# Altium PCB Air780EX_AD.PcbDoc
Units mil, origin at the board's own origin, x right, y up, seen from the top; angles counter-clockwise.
Board outline 6000 x 4000 mil, 4 copper layers (Top, Mid-Layer 1, Mid-Layer 2, Bottom), stack 35.4 mil thick; 1 components, 0 nets, 54 pads, 0 vias.
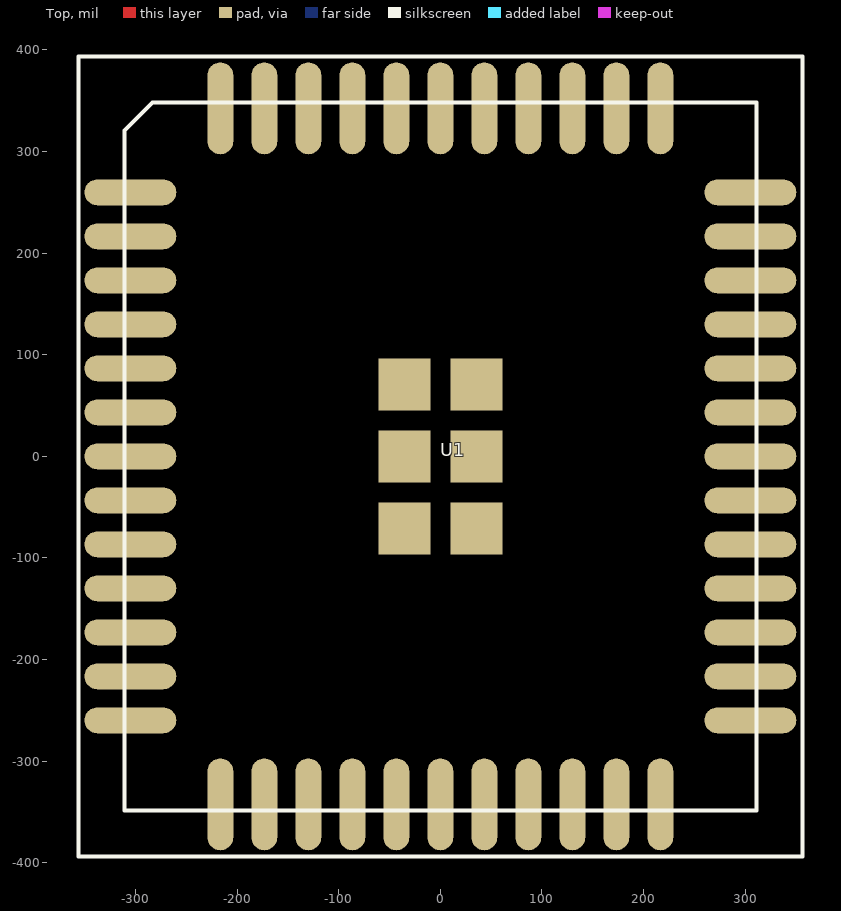
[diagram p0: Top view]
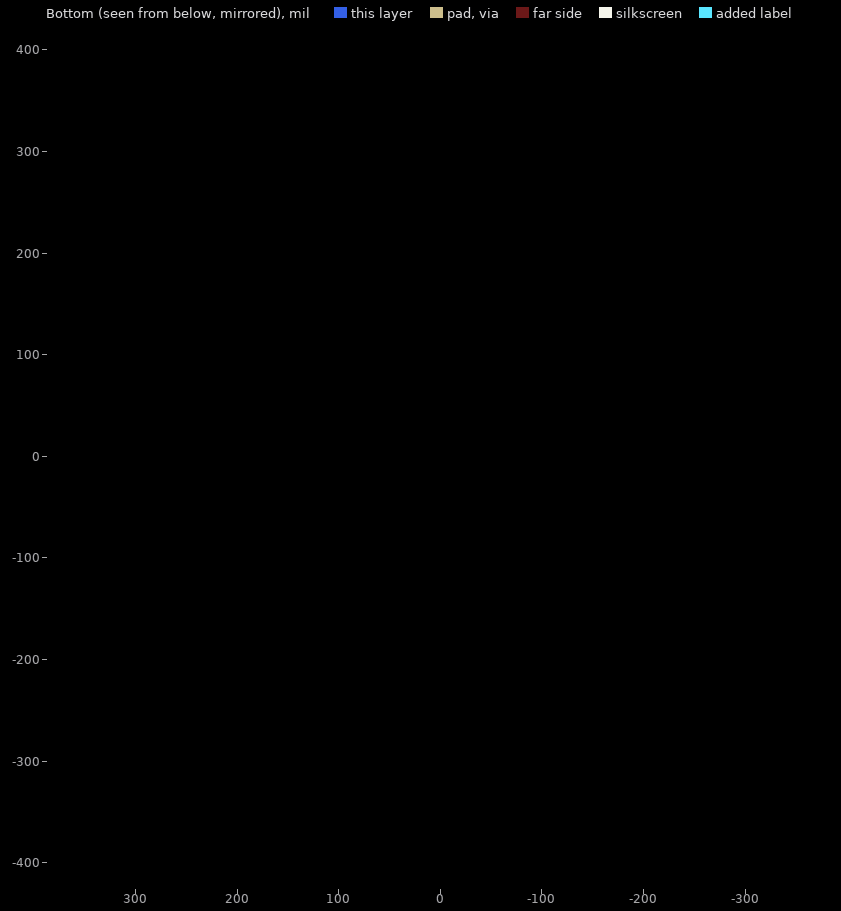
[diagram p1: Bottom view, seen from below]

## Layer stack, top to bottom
Top: signal copper 1.35
Dielectric: dielectric 10, FR-4, Dk 4.3
Mid-Layer 1: signal copper 1.35
Dielectric: dielectric 10, FR-4, Dk 4.3
Mid-Layer 2: signal copper 1.35
Dielectric: dielectric 10, FR-4, Dk 4.3
Bottom: signal copper 1.35

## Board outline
-9000,-9000 -3000,-9000 -3000,-5000 -9000,-5000

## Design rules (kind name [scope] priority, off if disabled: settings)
Clearance "'Default' PADS rule_18" [All] p1: gap=6
Clearance "'Default' PADS rule_15" [IsVia vs IsVia] p2: gap=6
ComponentClearance "'Default' PADS rule_12" [All] p1: gap=6 collisioncheckmode=3 verticalgap=10 showdistances=FALSE
FlightTimeFalling "'Default' PADS rule_10" [All] p1: maximum=10.00
FlightTimeRising "'Default' PADS rule_9" [All] p1: maximum=10.00
Length "'Default' PADS rule_5" [All] p1: maxlimit=50000 minlimit=0
MatchedLengths "'Default' PADS rule_11" [InNetClass('All Nets')] p1: tolerance=200 checknetsindiffpair=TRUE checkdiffpairvsdiffpair=TRUE checkothers=TRUE
MaxMinImpedance "'Default' PADS rule_8" [All] p1: minimum=50.00 maximum=150.0
ParallelSegment "'Default' PADS rule_7" [All] p1: limit=1000 gap=200
ParallelSegment "'Default' PADS rule_6" [All] p2: limit=1000 gap=200
PlaneClearance "'Default' PADS rule_14" [All] p1: clearance=6
PlaneConnect "Power Plane Connect Style - Via from round thru-hole global defaults" [IsVia] p1: planeconnectstyle=Relief reliefexpansion=20 reliefentries=4 reliefconductorwidth=15 reliefairgap=10
PlaneConnect "Power Plane Connect Style - Round thru-hole pad from global defaults" [IsPad And OnMultiLayer And (PadShape_MidLayer1 = 'Round') And (PadXSize_MidLayer1 = PadYSize_MidLayer1)] p2: planeconnectstyle=Relief reliefexpansion=20 reliefentries=4 reliefconductorwidth=15 reliefairgap=10
PlaneConnect "Power Plane Connect Style - Square thru-hole pad from global defaults" [IsPad And OnMultiLayer And ((PadShape_MidLayer1 = 'Rectangular') Or (PadShape_MidLayer1 = 'Octagonal') Or (PadShape_MidLayer1 = 'Rounded Rectangle')) And (PadXSize_MidLayer1 = PadYSize_MidLayer1)] p3: planeconnectstyle=Relief reliefexpansion=20 reliefentries=4 reliefconductorwidth=15 reliefairgap=10
PlaneConnect "Power Plane Connect Style - Rect thru-hole pad from global defaults" [IsPad And OnMultiLayer And ((PadShape_MidLayer1 = 'Rectangular') Or (PadShape_MidLayer1 = 'Octagonal') Or (PadShape_MidLayer1 = 'Rounded Rectangle')) And (PadXSize_MidLayer1 <> PadYSize_MidLayer1)] p4: planeconnectstyle=Relief reliefexpansion=20 reliefentries=4 reliefconductorwidth=15 reliefairgap=10
PlaneConnect "Power Plane Connect Style - Square-rect thru-hole pad from global defaults" [IsPad And OnMultiLayer And (PadShape_MidLayer1 = 'Rounded Rectangle') And (PadXSize_MidLayer1 = PadYSize_MidLayer1) And (Pad_CornerRadius_MidLayer1 = '0%')] p5: planeconnectstyle=Relief reliefexpansion=20 reliefentries=4 reliefconductorwidth=15 reliefairgap=10
PlaneConnect "Power Plane Connect Style - Oval thru-hole pad from global defaults" [IsPad And OnMultiLayer And (PadShape_MidLayer1 = 'Round') And (PadXSize_MidLayer1 <> PadYSize_MidLayer1)] p6: planeconnectstyle=Relief reliefexpansion=20 reliefentries=4 reliefconductorwidth=15 reliefairgap=10
PlaneConnect "Power Plane Connect Style - Round-oval thru-hole pad from global defaults" [IsPad And OnMultiLayer And (PadShape_MidLayer1 = 'Rounded Rectangle') And (PadXSize_MidLayer1 = PadYSize_MidLayer1) And (Pad_CornerRadius_MidLayer1 = '100%')] p7: planeconnectstyle=Relief reliefexpansion=20 reliefentries=4 reliefconductorwidth=15 reliefairgap=10
PolygonConnect "Polygon Connect Style - Bottom Round SMD from global defaults" [IsSMTPin And (PadShape_BottomLayer = 'Round') And (PadXSize_BottomLayer = PADYSize_BottomLayer) vs Layer = 'Bottom'] p1: connectstyle=Relief reliefconductorwidth=10 reliefentries=4 polygonreliefangle="45 Angle" airgapwidth=10
PolygonConnect "Polygon Connect Style - Top Round SMD from global defaults" [IsSMTPin And (PadShape_TopLayer = 'Round') And (PadXSize_TopLayer = PADYSize_TopLayer) vs Layer = 'Top'] p2: connectstyle=Relief reliefconductorwidth=10 reliefentries=4 polygonreliefangle="45 Angle" airgapwidth=10
PolygonConnect "Polygon Connect Style - Bottom Square SMD from global defaults 1" [IsSMTPin And (PadShape_BottomLayer = 'Rectangular') And (PadXSize_BottomLayer = PADYSize_BottomLayer) vs Layer = 'Bottom'] p3: connectstyle=Relief reliefconductorwidth=10 reliefentries=4 polygonreliefangle="45 Angle" airgapwidth=10
PolygonConnect "Polygon Connect Style - Bottom Square SMD from global defaults 2" [IsSMTPin And (PadShape_BottomLayer = 'Octagonal') And (PadXSize_BottomLayer = PADYSize_BottomLayer) vs Layer = 'Bottom'] p4: connectstyle=Relief reliefconductorwidth=10 reliefentries=4 polygonreliefangle="45 Angle" airgapwidth=10
PolygonConnect "Polygon Connect Style - Bottom Square SMD from global defaults 3" [IsSMTPin And (PadShape_BottomLayer = 'Rounded Rectangle') And (PadXSize_BottomLayer = PADYSize_BottomLayer) vs Layer = 'Bottom'] p5: connectstyle=Relief reliefconductorwidth=10 reliefentries=4 polygonreliefangle="45 Angle" airgapwidth=10
PolygonConnect "Polygon Connect Style - Top Square SMD from global defaults 1" [IsSMTPin And (PadShape_TopLayer = 'Rectangular') And (PadXSize_TopLayer = PADYSize_TopLayer) vs Layer = 'Top'] p6: connectstyle=Relief reliefconductorwidth=10 reliefentries=4 polygonreliefangle="45 Angle" airgapwidth=10
PolygonConnect "Polygon Connect Style - Top Square SMD from global defaults 2" [IsSMTPin And (PadShape_TopLayer = 'Octagonal') And (PadXSize_TopLayer = PADYSize_TopLayer) vs Layer = 'Top'] p7: connectstyle=Relief reliefconductorwidth=10 reliefentries=4 polygonreliefangle="45 Angle" airgapwidth=10
PolygonConnect "Polygon Connect Style - Top Square SMD from global defaults 3" [IsSMTPin And (PadShape_TopLayer = 'Rounded Rectangle') And (PadXSize_TopLayer = PADYSize_TopLayer) vs Layer = 'Top'] p8: connectstyle=Relief reliefconductorwidth=10 reliefentries=4 polygonreliefangle="45 Angle" airgapwidth=10
PolygonConnect "Polygon Connect Style - Bottom Rect SMD from global defaults 1" [IsSMTPin And (PadShape_BottomLayer = 'Rectangular') And (PadXSize_BottomLayer <> PADYSize_BottomLayer) vs Layer = 'Bottom'] p9: connectstyle=Relief reliefconductorwidth=10 reliefentries=4 polygonreliefangle="45 Angle" airgapwidth=10
PolygonConnect "Polygon Connect Style - Bottom Rect SMD from global defaults 2" [IsSMTPin And (PadShape_BottomLayer = 'Octagonal') And (PadXSize_BottomLayer <> PADYSize_BottomLayer) vs Layer = 'Bottom'] p10: connectstyle=Relief reliefconductorwidth=10 reliefentries=4 polygonreliefangle="45 Angle" airgapwidth=10
PolygonConnect "Polygon Connect Style - Bottom Rect SMD from global defaults 3" [IsSMTPin And (PadShape_BottomLayer = 'Rounded Rectangle') And (PadXSize_BottomLayer <> PADYSize_BottomLayer) vs Layer = 'Bottom'] p11: connectstyle=Relief reliefconductorwidth=10 reliefentries=4 polygonreliefangle="45 Angle" airgapwidth=10
PolygonConnect "Polygon Connect Style - Bottom Square-rect SMD pad from global defaults" [IsSMTPin And (PadShape_BottomLayer = 'Rounded Rectangle') And (PadXSize_BottomLayer = PADYSize_BottomLayer) And (Pad_CornerRadius_BottomLayer = '0%') vs Layer = 'Bottom'] p12: connectstyle=Relief reliefconductorwidth=10 reliefentries=4 polygonreliefangle="45 Angle" airgapwidth=10
PolygonConnect "Polygon Connect Style - Top Rect SMD from global defaults 1" [IsSMTPin And (PadShape_TopLayer = 'Rectangular') And (PadXSize_TopLayer <> PADYSize_TopLayer) vs Layer = 'Top'] p13: connectstyle=Relief reliefconductorwidth=10 reliefentries=4 polygonreliefangle="45 Angle" airgapwidth=10
PolygonConnect "Polygon Connect Style - Top Rect SMD from global defaults 2" [IsSMTPin And (PadShape_TopLayer = 'Octagonal') And (PadXSize_TopLayer <> PADYSize_TopLayer) vs Layer = 'Top'] p14: connectstyle=Relief reliefconductorwidth=10 reliefentries=4 polygonreliefangle="45 Angle" airgapwidth=10
PolygonConnect "Polygon Connect Style - Top Rect SMD from global defaults 3" [IsSMTPin And (PadShape_TopLayer = 'Rounded Rectangle') And (PadXSize_TopLayer <> PADYSize_TopLayer) vs Layer = 'Top'] p15: connectstyle=Relief reliefconductorwidth=10 reliefentries=4 polygonreliefangle="45 Angle" airgapwidth=10
PolygonConnect "Polygon Connect Style - Top Square-rect SMD pad from global defaults" [IsSMTPin And (PadShape_TopLayer = 'Rounded Rectangle') And (PadXSize_TopLayer = PADYSize_TopLayer) And (Pad_CornerRadius_TopLayer = '0%') vs Layer = 'Top'] p16: connectstyle=Relief reliefconductorwidth=10 reliefentries=4 polygonreliefangle="45 Angle" airgapwidth=10
PolygonConnect "Polygon Connect Style - Bottom Oval SMD from global defaults" [IsSMTPin And (PadShape_BottomLayer = 'Round') And (PadXSize_BottomLayer <> PADYSize_BottomLayer) vs Layer = 'Bottom'] p17: connectstyle=Relief reliefconductorwidth=10 reliefentries=4 polygonreliefangle="45 Angle" airgapwidth=10
PolygonConnect "Polygon Connect Style - Bottom Round-oval SMD pad from global defaults" [IsSMTPin And (PadShape_BottomLayer = 'Rounded Rectangle') And (PadXSize_BottomLayer = PADYSize_BottomLayer) And (Pad_CornerRadius_BottomLayer = '100%') vs Layer = 'Bottom'] p18: connectstyle=Relief reliefconductorwidth=10 reliefentries=4 polygonreliefangle="45 Angle" airgapwidth=10
PolygonConnect "Polygon Connect Style - Top Oval SMD from global defaults" [IsSMTPin And (PadShape_TopLayer = 'Round') And (PadXSize_TopLayer <> PADYSize_TopLayer) vs Layer = 'Top'] p19: connectstyle=Relief reliefconductorwidth=10 reliefentries=4 polygonreliefangle="45 Angle" airgapwidth=10
PolygonConnect "Polygon Connect Style - Top Round-oval SMD pad from global defaults" [IsSMTPin And (PadShape_TopLayer = 'Rounded Rectangle') And (PadXSize_TopLayer = PADYSize_TopLayer) And (Pad_CornerRadius_TopLayer = '100%') vs Layer = 'Top'] p20: connectstyle=Relief reliefconductorwidth=10 reliefentries=4 polygonreliefangle="45 Angle" airgapwidth=10
PolygonConnect "Polygon Connect Style - Via from round thru-hole global defaults_21" [IsVia] p21: connectstyle=Relief reliefconductorwidth=15 reliefentries=4 polygonreliefangle="45 Angle" airgapwidth=10
PolygonConnect "Polygon Connect Style - Bottom Round thru-hole pad from global defaults" [IsPad And OnMultiLayer And (PadShape_BottomLayer = 'Round') And (PadXSize_BottomLayer = PADYSize_BottomLayer) vs Layer = 'Bottom'] p22: connectstyle=Relief reliefconductorwidth=15 reliefentries=4 polygonreliefangle="45 Angle" airgapwidth=10
PolygonConnect "Polygon Connect Style - Via from round thru-hole global defaults_20" [IsVia] p23: connectstyle=Relief reliefconductorwidth=15 reliefentries=4 polygonreliefangle="45 Angle" airgapwidth=10
PolygonConnect "Polygon Connect Style - Mid-Layer 2 Round thru-hole pad from global defaults" [IsPad And OnMultiLayer And (PadShape_MidLayer2 = 'Round') And (PadXSize_MidLayer2 = PADYSize_MidLayer2) vs Layer = 'Mid-Layer 2'] p24: connectstyle=Relief reliefconductorwidth=15 reliefentries=4 polygonreliefangle="45 Angle" airgapwidth=10
PolygonConnect "Polygon Connect Style - Via from round thru-hole global defaults_19" [IsVia] p25: connectstyle=Relief reliefconductorwidth=15 reliefentries=4 polygonreliefangle="45 Angle" airgapwidth=10
PolygonConnect "Polygon Connect Style - Mid-Layer 1 Round thru-hole pad from global defaults" [IsPad And OnMultiLayer And (PadShape_MidLayer1 = 'Round') And (PadXSize_MidLayer1 = PADYSize_MidLayer1) vs Layer = 'Mid-Layer 1'] p26: connectstyle=Relief reliefconductorwidth=15 reliefentries=4 polygonreliefangle="45 Angle" airgapwidth=10
PolygonConnect "Polygon Connect Style - Via from round thru-hole global defaults" [IsVia] p27: connectstyle=Relief reliefconductorwidth=15 reliefentries=4 polygonreliefangle="45 Angle" airgapwidth=10
PolygonConnect "Polygon Connect Style - Top Round thru-hole pad from global defaults" [IsPad And OnMultiLayer And (PadShape_TopLayer = 'Round') And (PadXSize_TopLayer = PADYSize_TopLayer) vs Layer = 'Top'] p28: connectstyle=Relief reliefconductorwidth=15 reliefentries=4 polygonreliefangle="45 Angle" airgapwidth=10
PolygonConnect "Polygon Connect Style - Bottom Square thru-hole pad from global defaults" [IsPad And OnMultiLayer And ((PadShape_BottomLayer = 'Rectangular') Or (PadShape_BottomLayer = 'Octagonal') Or (PadShape_BottomLayer = 'Rounded Rectangle')) And (PadXSize_BottomLayer = PADYSize_BottomLayer) vs Layer = 'Bottom'] p29: connectstyle=Relief reliefconductorwidth=15 reliefentries=4 polygonreliefangle="45 Angle" airgapwidth=10
PolygonConnect "Polygon Connect Style - Mid-Layer 2 Square thru-hole pad from global defaults" [IsPad And OnMultiLayer And ((PadShape_MidLayer2 = 'Rectangular') Or (PadShape_MidLayer2 = 'Octagonal') Or (PadShape_MidLayer2 = 'Rounded Rectangle')) And (PadXSize_MidLayer2 = PADYSize_MidLayer2) vs Layer = 'Mid-Layer 2'] p30: connectstyle=Relief reliefconductorwidth=15 reliefentries=4 polygonreliefangle="45 Angle" airgapwidth=10
PolygonConnect "Polygon Connect Style - Mid-Layer 1 Square thru-hole pad from global defaults" [IsPad And OnMultiLayer And ((PadShape_MidLayer1 = 'Rectangular') Or (PadShape_MidLayer1 = 'Octagonal') Or (PadShape_MidLayer1 = 'Rounded Rectangle')) And (PadXSize_MidLayer1 = PADYSize_MidLayer1) vs Layer = 'Mid-Layer 1'] p31: connectstyle=Relief reliefconductorwidth=15 reliefentries=4 polygonreliefangle="45 Angle" airgapwidth=10
PolygonConnect "Polygon Connect Style - Top Square thru-hole pad from global defaults" [IsPad And OnMultiLayer And ((PadShape_TopLayer = 'Rectangular') Or (PadShape_TopLayer = 'Octagonal') Or (PadShape_TopLayer = 'Rounded Rectangle')) And (PadXSize_TopLayer = PADYSize_TopLayer) vs Layer = 'Top'] p32: connectstyle=Relief reliefconductorwidth=15 reliefentries=4 polygonreliefangle="45 Angle" airgapwidth=10
PolygonConnect "Polygon Connect Style - Bottom Rect thru-hole pad from global defaults" [IsPad And OnMultiLayer And ((PadShape_BottomLayer = 'Rectangular') Or (PadShape_BottomLayer = 'Octagonal') Or (PadShape_BottomLayer = 'Rounded Rectangle')) And (PadXSize_BottomLayer <> PADYSize_BottomLayer) vs Layer = 'Bottom'] p33: connectstyle=Relief reliefconductorwidth=15 reliefentries=4 polygonreliefangle="45 Angle" airgapwidth=10
PolygonConnect "Polygon Connect Style - Bottom Square-rect thru-hole pad from global defaults" [IsPad And OnMultiLayer And (PadShape_BottomLayer = 'Rounded Rectangle') And (PadXSize_BottomLayer = PADYSize_BottomLayer) And (Pad_CornerRadius_BottomLayer = '0%') vs Layer = 'Bottom'] p34: connectstyle=Relief reliefconductorwidth=15 reliefentries=4 polygonreliefangle="45 Angle" airgapwidth=10
PolygonConnect "Polygon Connect Style - Mid-Layer 2 Rect thru-hole pad from global defaults" [IsPad And OnMultiLayer And ((PadShape_MidLayer2 = 'Rectangular') Or (PadShape_MidLayer2 = 'Octagonal') Or (PadShape_MidLayer2 = 'Rounded Rectangle')) And (PadXSize_MidLayer2 <> PADYSize_MidLayer2) vs Layer = 'Mid-Layer 2'] p35: connectstyle=Relief reliefconductorwidth=15 reliefentries=4 polygonreliefangle="45 Angle" airgapwidth=10
PolygonConnect "Polygon Connect Style - Mid-Layer 2 Square-rect thru-hole pad from global defaults" [IsPad And OnMultiLayer And (PadShape_MidLayer2 = 'Rounded Rectangle') And (PadXSize_MidLayer2 = PADYSize_MidLayer2) And (Pad_CornerRadius_MidLayer2 = '0%') vs Layer = 'Mid-Layer 2'] p36: connectstyle=Relief reliefconductorwidth=15 reliefentries=4 polygonreliefangle="45 Angle" airgapwidth=10
PolygonConnect "Polygon Connect Style - Mid-Layer 1 Rect thru-hole pad from global defaults" [IsPad And OnMultiLayer And ((PadShape_MidLayer1 = 'Rectangular') Or (PadShape_MidLayer1 = 'Octagonal') Or (PadShape_MidLayer1 = 'Rounded Rectangle')) And (PadXSize_MidLayer1 <> PADYSize_MidLayer1) vs Layer = 'Mid-Layer 1'] p37: connectstyle=Relief reliefconductorwidth=15 reliefentries=4 polygonreliefangle="45 Angle" airgapwidth=10
PolygonConnect "Polygon Connect Style - Mid-Layer 1 Square-rect thru-hole pad from global defaults" [IsPad And OnMultiLayer And (PadShape_MidLayer1 = 'Rounded Rectangle') And (PadXSize_MidLayer1 = PADYSize_MidLayer1) And (Pad_CornerRadius_MidLayer1 = '0%') vs Layer = 'Mid-Layer 1'] p38: connectstyle=Relief reliefconductorwidth=15 reliefentries=4 polygonreliefangle="45 Angle" airgapwidth=10
PolygonConnect "Polygon Connect Style - Top Rect thru-hole pad from global defaults" [IsPad And OnMultiLayer And ((PadShape_TopLayer = 'Rectangular') Or (PadShape_TopLayer = 'Octagonal') Or (PadShape_TopLayer = 'Rounded Rectangle')) And (PadXSize_TopLayer <> PADYSize_TopLayer) vs Layer = 'Top'] p39: connectstyle=Relief reliefconductorwidth=15 reliefentries=4 polygonreliefangle="45 Angle" airgapwidth=10
PolygonConnect "Polygon Connect Style - Top Square-rect thru-hole pad from global defaults" [IsPad And OnMultiLayer And (PadShape_TopLayer = 'Rounded Rectangle') And (PadXSize_TopLayer = PADYSize_TopLayer) And (Pad_CornerRadius_TopLayer = '0%') vs Layer = 'Top'] p40: connectstyle=Relief reliefconductorwidth=15 reliefentries=4 polygonreliefangle="45 Angle" airgapwidth=10
PolygonConnect "Polygon Connect Style - Bottom Oval thru-hole pad from global defaults" [IsPad And OnMultiLayer And (PadShape_BottomLayer = 'Round') And (PadXSize_BottomLayer <> PADYSize_BottomLayer) vs Layer = 'Bottom'] p41: connectstyle=Relief reliefconductorwidth=15 reliefentries=4 polygonreliefangle="45 Angle" airgapwidth=10
PolygonConnect "Polygon Connect Style - Bottom Round-oval thru-hole pad from global defaults" [IsPad And OnMultiLayer And (PadShape_BottomLayer = 'Rounded Rectangle') And (PadXSize_BottomLayer = PADYSize_BottomLayer) And (Pad_CornerRadius_BottomLayer = '100%') vs Layer = 'Bottom'] p42: connectstyle=Relief reliefconductorwidth=15 reliefentries=4 polygonreliefangle="45 Angle" airgapwidth=10
PolygonConnect "Polygon Connect Style - Mid-Layer 2 Oval thru-hole pad from global defaults" [IsPad And OnMultiLayer And (PadShape_MidLayer2 = 'Round') And (PadXSize_MidLayer2 <> PADYSize_MidLayer2) vs Layer = 'Mid-Layer 2'] p43: connectstyle=Relief reliefconductorwidth=15 reliefentries=4 polygonreliefangle="45 Angle" airgapwidth=10
PolygonConnect "Polygon Connect Style - Mid-Layer 2 Round-oval thru-hole pad from global defaults" [IsPad And OnMultiLayer And (PadShape_MidLayer2 = 'Rounded Rectangle') And (PadXSize_MidLayer2 = PADYSize_MidLayer2) And (Pad_CornerRadius_MidLayer2 = '100%') vs Layer = 'Mid-Layer 2'] p44: connectstyle=Relief reliefconductorwidth=15 reliefentries=4 polygonreliefangle="45 Angle" airgapwidth=10
PolygonConnect "Polygon Connect Style - Mid-Layer 1 Oval thru-hole pad from global defaults" [IsPad And OnMultiLayer And (PadShape_MidLayer1 = 'Round') And (PadXSize_MidLayer1 <> PADYSize_MidLayer1) vs Layer = 'Mid-Layer 1'] p45: connectstyle=Relief reliefconductorwidth=15 reliefentries=4 polygonreliefangle="45 Angle" airgapwidth=10
PolygonConnect "Polygon Connect Style - Mid-Layer 1 Round-oval thru-hole pad from global defaults" [IsPad And OnMultiLayer And (PadShape_MidLayer1 = 'Rounded Rectangle') And (PadXSize_MidLayer1 = PADYSize_MidLayer1) And (Pad_CornerRadius_MidLayer1 = '100%') vs Layer = 'Mid-Layer 1'] p46: connectstyle=Relief reliefconductorwidth=15 reliefentries=4 polygonreliefangle="45 Angle" airgapwidth=10
PolygonConnect "Polygon Connect Style - Top Oval thru-hole pad from global defaults" [IsPad And OnMultiLayer And (PadShape_TopLayer = 'Round') And (PadXSize_TopLayer <> PADYSize_TopLayer) vs Layer = 'Top'] p47: connectstyle=Relief reliefconductorwidth=15 reliefentries=4 polygonreliefangle="45 Angle" airgapwidth=10
PolygonConnect "Polygon Connect Style - Top Round-oval thru-hole pad from global defaults" [IsPad And OnMultiLayer And (PadShape_TopLayer = 'Rounded Rectangle') And (PadXSize_TopLayer = PADYSize_TopLayer) And (Pad_CornerRadius_TopLayer = '100%') vs Layer = 'Top'] p48: connectstyle=Relief reliefconductorwidth=15 reliefentries=4 polygonreliefangle="45 Angle" airgapwidth=10
PolygonConnect [All] p49: connectstyle=Relief reliefconductorwidth=10 reliefentries=4 polygonreliefangle="90 Angle" airgapwidth=10
RoutingLayers "'Default' PADS rule_3" [All] p1: top layer_v5=TRUE mid layer 1_v5=TRUE mid layer 2_v5=TRUE bottom layer_v5=TRUE
RoutingPriority "'Default' PADS rule_2" [All] p1: routingpriority=3
RoutingTopology "'Default' PADS rule" [All] p1: topology=Shortest
RoutingVias "'Default' PADS rule_4" [All] p1: holewidth=37 width=55 viastyle="Through Hole" minholewidth=37 minwidth=55 maxholewidth=37 maxwidth=55
SMDToCorner "'Default' PADS rule_16" [All] p1: distance=60000
SMDToPlane "'Default' PADS rule_17" [All] p1: distance=60000
SolderMaskExpansion [All] p1: expansion=4
Width "'Default' PADS rule_13" [All] p1: maxlimit=12 minlimit=12 preferedwidth=12
22 further rules are at their usual default settings.

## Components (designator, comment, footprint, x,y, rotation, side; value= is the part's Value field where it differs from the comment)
U1 "AIR780EX" AIR780EX 0,0 r0 top

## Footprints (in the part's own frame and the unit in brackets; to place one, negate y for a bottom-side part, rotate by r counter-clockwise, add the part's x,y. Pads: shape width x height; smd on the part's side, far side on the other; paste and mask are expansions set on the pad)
AIR780EX [mm]
  oval 2.3x0.65 smd: 1(-7.75,6.6) 2(-7.75,5.5) 3(-7.75,4.4) 4(-7.75,3.3) 5(-7.75,2.2) 6(-7.75,1.1) 7(-7.75,0) 8(-7.75,-1.1) 9(-7.75,-2.2) 10(-7.75,-3.3) 11(-7.75,-4.4) 12(-7.75,-5.5) 13(-7.75,-6.6) 23(7.75,-6.6) 24(7.75,-5.5) 25(7.75,-4.4) 26(7.75,-3.3) 27(7.75,-2.2) 28(7.75,-1.1) 29(7.75,0) 30(7.75,1.1) 31(7.75,2.2) 32(7.75,3.3) 33(7.75,4.4) 34(7.75,5.5) 35(7.75,6.6)
  oval 0.65x2.3 smd: 14(-4.4,-8.7) 15(-3.3,-8.7) 16(-2.2,-8.7) 17(-1.1,-8.7) 18(0,-8.7) 19(1.1,-8.7) 20(2.2,-8.7) 21(3.3,-8.7) 22(4.4,-8.7) 36(4.4,8.7) 37(3.3,8.7) 38(2.2,8.7) 39(1.1,8.7) 40(0,8.7) 41(-1.1,8.7) 42(-2.2,8.7) 43(-3.3,8.7) 44(-4.4,8.7) 95(-5.5,-8.7) 96(5.5,-8.7) 97(5.5,8.7) 98(-5.5,8.7)
  rect 1.3x1.3 smd: 89(-0.9,1.8) 90(-0.9,0) 91(-0.9,-1.8) 92(0.9,-1.8) 93(0.9,0) 94(0.9,1.8)
  silkscreen extent -9.05,-10 9.05,10

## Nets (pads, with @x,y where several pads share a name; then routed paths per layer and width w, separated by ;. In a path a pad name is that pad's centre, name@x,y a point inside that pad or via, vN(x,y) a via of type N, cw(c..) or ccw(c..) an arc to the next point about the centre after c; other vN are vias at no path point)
pads on no net: U1.1 U1.2 U1.3 U1.4 U1.5 U1.6 U1.7 U1.8 U1.9 U1.10 U1.11 U1.12 U1.13 U1.14 U1.15 U1.16 U1.17 U1.18 U1.19 U1.20 U1.21 U1.22 U1.23 U1.24 U1.25 U1.26 U1.27 U1.28 U1.29 U1.30 U1.31 U1.32 U1.33 U1.34 U1.35 U1.36 U1.37 U1.38 U1.39 U1.40 U1.41 U1.42 U1.43 U1.44 U1.89 U1.90 U1.91 U1.92 U1.93 U1.94 U1.95 U1.96 U1.97 U1.98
